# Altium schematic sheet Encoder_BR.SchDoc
size A4; Date: 09 July 2012; Author: Simon Markham; DrawnBy: Simon Markham; Engineer: Simon Markham; Organization: Markham Designs
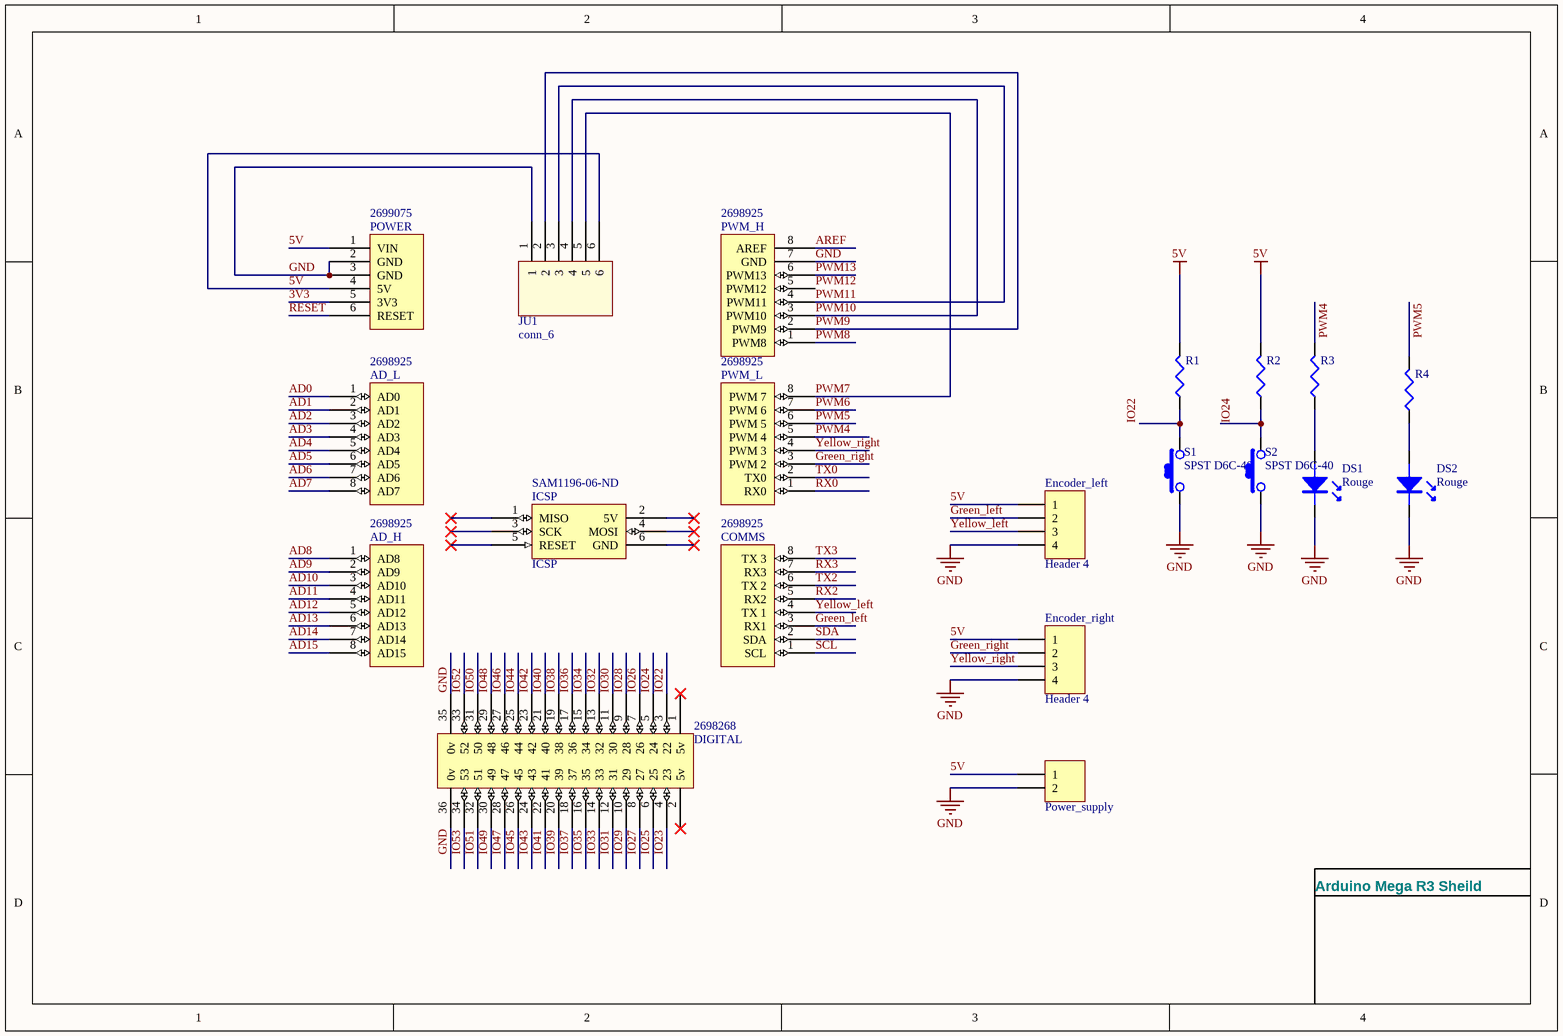
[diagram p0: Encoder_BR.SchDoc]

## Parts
AD_H  Supplier Part Number 4: 2698925  [Header 8x1 8.5mm]  (hidden comment: AD_H)
AD_L  Supplier Part Number 5: 2698925  [Header 8x1 8.5mm]  (hidden comment: AD_L)
COMMS  Supplier Part Number 4: 2698925  [Header 8x1 8.5mm]  (hidden comment: Communication)
DIGITAL  Supplier Part Number 5: 2698268  [HEADER 36X 8MM]  (hidden comment: IO_36)
DS1  Color: Rouge  [LED 0.1]  (hidden comment: LED)
DS2  Color: Rouge  [LED 0.1]  (hidden comment: LED)
Encoder_left  Header 4  [Header_4]
Encoder_right  Header 4  [Header_4]
ICSP  ICSP  Supplier Part Number 5: SAM1196-06-ND  [ICSP]
JU1  conn_6  [conn_6]
POWER  Supplier Part Number 2: 2699075  [Header 6x1 8.5mm]  (hidden comment: POWER)
Power_supply  Connecteur 2  [Header_2]  (value not drawn)
PWM_H  Supplier Part Number 4: 2698925  [Header 8x1 8.5mm]  (hidden comment: PWM_H)
PWM_L  Supplier Part Number 4: 2698925  [Header 8x1 8.5mm]  (hidden comment: PWM_L)
R1  Résistance  [AXIAL-0.3]  (value not drawn)
R2  Résistance  [AXIAL-0.3]  (value not drawn)
R3  Résistance  [AXIAL-0.3]  (value not drawn)
R4  Résistance  [AXIAL-0.3]  (value not drawn)
S1  Type: SPST D6C-40  [BP-D6 SPST]  (hidden comment: Bouton Poussoir D6)
S2  Type: SPST D6C-40  [BP-D6 SPST]  (hidden comment: Bouton Poussoir D6)

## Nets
5V: Encoder_left.1 Encoder_right.1 JU1.6 POWER.1(VIN) POWER.4(5V) Power_supply.1 R1.2 R2.2
GND: DIGITAL.35(0v) DIGITAL.36(0v) DS1.2(K) DS2.2(K) Encoder_left.4 Encoder_right.4 JU1.1 POWER.2(GND) POWER.3(GND) Power_supply.2 PWM_H.7(GND) S1.1 S2.1
3V3: POWER.5(3V3)
AD0: AD_L.1(AD0)
AD1: AD_L.2(AD1)
AD2: AD_L.3(AD2)
AD3: AD_L.4(AD3)
AD4: AD_L.5(AD4)
AD5: AD_L.6(AD5)
AD6: AD_L.7(AD6)
AD7: AD_L.8(AD7)
AD8: AD_H.1(AD8)
AD9: AD_H.2(AD9)
AD10: AD_H.3(AD10)
AD11: AD_H.4(AD11)
AD12: AD_H.5(AD12)
AD13: AD_H.6(AD13)
AD14: AD_H.7(AD14)
AD15: AD_H.8(AD15)
AREF: PWM_H.8(AREF)
Green_left: COMMS.3(RX1) Encoder_left.2
Green_right: Encoder_right.2 PWM_L.3(PWM_2)
IO22: DIGITAL.3(22) R1.1 S1.2
IO23: DIGITAL.4(23)
IO24: DIGITAL.5(24) R2.1 S2.2
IO25: DIGITAL.6(25)
IO26: DIGITAL.7(26)
IO27: DIGITAL.8(27)
IO28: DIGITAL.9(28)
IO29: DIGITAL.10(29)
IO30: DIGITAL.11(30)
IO31: DIGITAL.12(31)
IO32: DIGITAL.13(32)
IO33: DIGITAL.14(33)
IO34: DIGITAL.15(34)
IO35: DIGITAL.16(35)
IO36: DIGITAL.17(36)
IO37: DIGITAL.18(37)
IO38: DIGITAL.19(38)
IO39: DIGITAL.20(39)
IO40: DIGITAL.21(40)
IO41: DIGITAL.22(41)
IO42: DIGITAL.23(42)
IO43: DIGITAL.24(43)
IO44: DIGITAL.25(44)
IO45: DIGITAL.26(45)
IO46: DIGITAL.27(46)
IO47: DIGITAL.28(47)
IO48: DIGITAL.29(48)
IO49: DIGITAL.30(49)
IO50: DIGITAL.31(50)
IO51: DIGITAL.32(51)
IO52: DIGITAL.33(52)
IO53: DIGITAL.34(53)
PWM4: PWM_L.5(PWM_4) R3.2
PWM5: PWM_L.6(PWM_5) R4.2
PWM6: PWM_L.7(PWM_6)
PWM7: JU1.5 PWM_L.8(PWM_7)
PWM8: PWM_H.1(PWM8)
PWM9: JU1.2 PWM_H.2(PWM9)
PWM10: JU1.4 PWM_H.3(PWM10)
PWM11: JU1.3 PWM_H.4(PWM11)
PWM12: PWM_H.5(PWM12)
PWM13: PWM_H.6(PWM13)
RESET: POWER.6(RESET)
RX0: PWM_L.1(RX0)
RX2: COMMS.5(RX2)
RX3: COMMS.7(RX3)
SCL: COMMS.1(SCL)
SDA: COMMS.2(SDA)
TX0: PWM_L.2(TX0)
TX2: COMMS.6(TX_2)
TX3: COMMS.8(TX_3)
Yellow_left: COMMS.4(TX_1) Encoder_left.3
Yellow_right: Encoder_right.3 PWM_L.4(PWM_3)
NetDS1_1: DS1.1(A) R3.1
NetDS2_1: DS2.1(A) R4.1

Not connected (* = marked no-connect by the designer): DIGITAL 1(5v)* 2(5v)*; ICSP 1(MISO)* 2(5V)* 3(SCK)* 4(MOSI)* 5(RESET)* 6(GND)*

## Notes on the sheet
- Arduino Mega R3 Sheild

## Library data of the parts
Encoder_left Encoder_right = Header 4: Header, 4-Pin
JU1 = conn_6: pin to pad: 1>2 2>3 3>4 4>5 5>6 6>1
Power_supply = Connecteur 2: Header 2
R1-R4 = Résistance: Résistance standard
S1 S2 = Bouton Poussoir D6: Bouton poussoir; Manufacturer: ITT CANON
